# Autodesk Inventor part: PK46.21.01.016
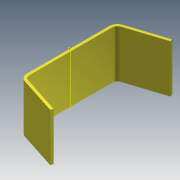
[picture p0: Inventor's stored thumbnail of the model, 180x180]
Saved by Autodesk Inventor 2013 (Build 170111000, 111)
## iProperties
Created: 2005-04
Part Number: PK46.21.01.016
Material: Steel, Mild
Document SubType Name: Листовой материал
Designer: salex
Manufacturer: Standard
Standards Organization: Custom
Density: 7.86 g/cm^3
Sheet Metal Rule: По умолчанию
Author: salex
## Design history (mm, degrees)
node "ФлнОтгиб1"
  sketch "Эскиз1"
    geometry: L1 (190.994, 220)-(35.994, 170); L2 (35.994, 170)-(35.994, -170); L3 (35.994, -170)-(190.994, -220); L4 (59.031, -92)-(59.031, 92) reference; L5 (35.994, 0)-(-34.832, 0)
    constraints: 10 end point, 2 vertical, 1 equal length, 1 midpoint, 1 perpendicular, 3 other
    dimensions: "d4" = 340 distance of L1.end L2.end; "d13" = 50 vertical distance of L3.end L2.end; "d14" = 155 horizontal distance of L2.end L3.end; "d15" = 50 vertical distance of L1.start L1.end (= d13)
node "РабПлоскость1"
body "Solid1"
feature "Плакирование1" dims "d6" = 180, "d7" = 10 (= Ширина_просечки), "d9" = 20 (= Минимальный_остаток), "d11" = 20 (= Радиус_гибки), "d12" = 10, "Толщина" = 10
feature "Изгиб1" dims "d7" = 10 (= Ширина_просечки), "d8" = 5 (= Глубина_просечки), "d9" = 20 (= Минимальный_остаток), "d10" = 20 (= Радиус_гибки), "d11" = 20 (= Радиус_гибки), "d12" = 10, "Толщина" = 10, "Зазор_стыка" = 0.01
other parameters: "Радиус_гибки" = 20, "Глубина_просечки" = 5 (= 0.5 x Толщина)
